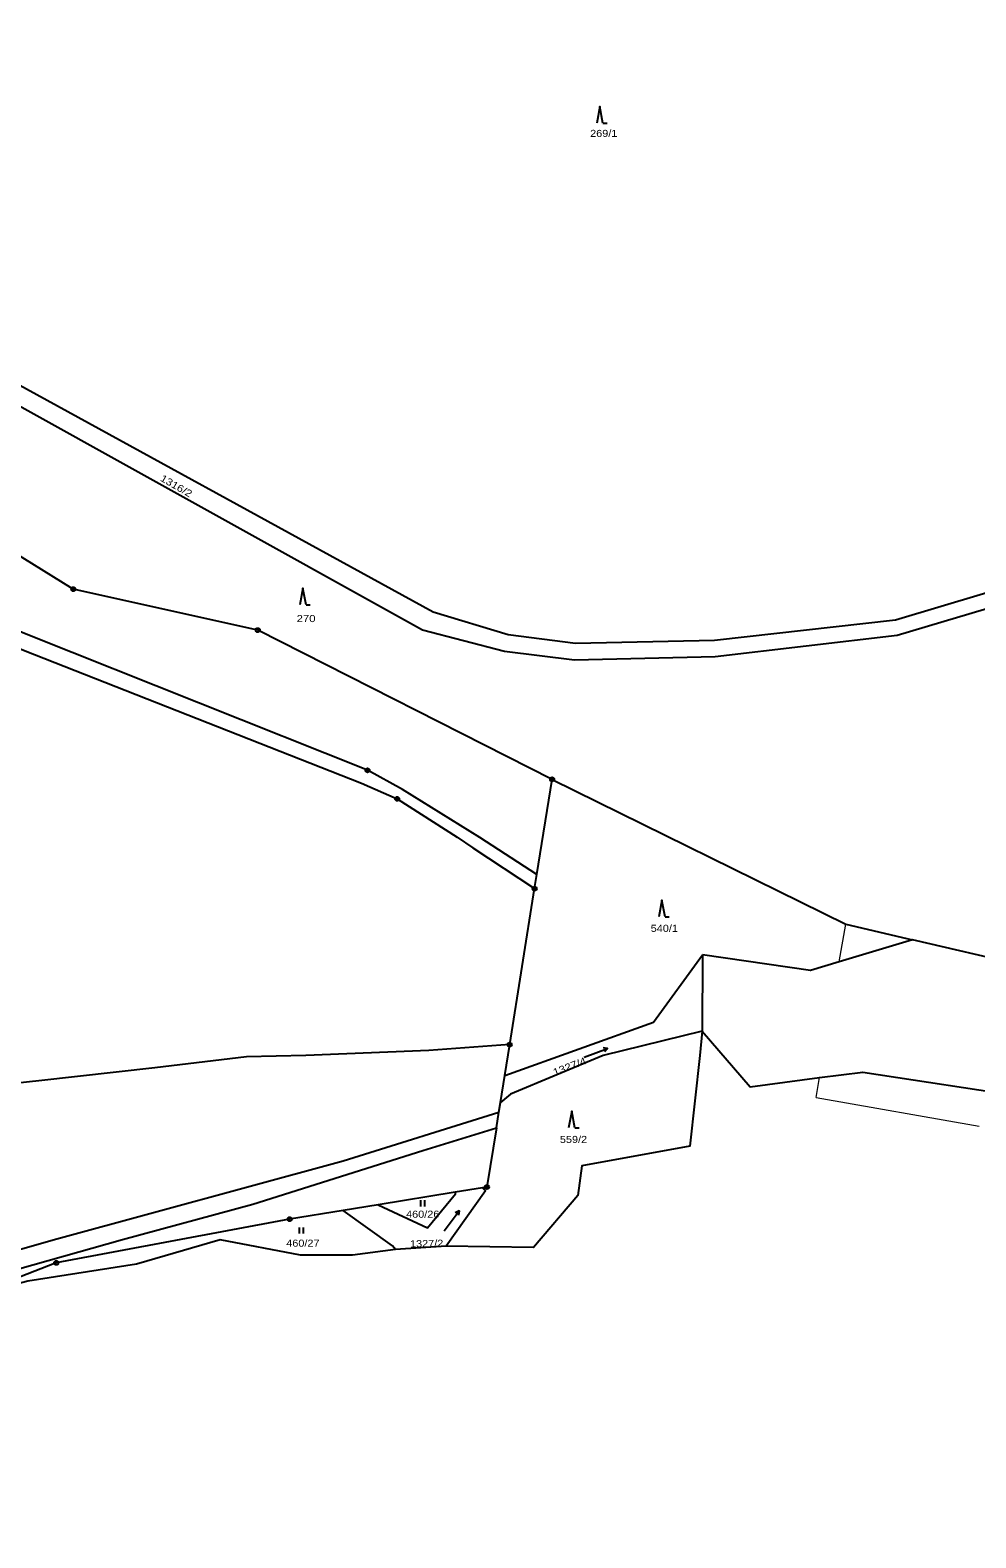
# Model space of a CAD drawing. Extents: x -872229 to -869198, y -1075981 to -1074329.
# Drawn here: x -869771.9 to -869544.7, y -1075316.1 to -1074953.6 of the extents above; entities that cross this region are included whole.
import ezdxf

# ---------------------------------------------------------------- set-up
doc = ezdxf.new("R2010")
doc.units = 0
doc.header["$LTSCALE"] = 0.68
for name, color, linetype, lineweight in [('1', 7, 'Continuous', 25), ('3', 7, 'Continuous', 25), ('4', 7, 'Continuous', 13), ('8', 7, 'Continuous', 25)]:
    doc.layers.add(name, color=color, linetype=linetype, lineweight=lineweight)
doc.layers.add('2', color=7, linetype='Continuous')

msp = doc.modelspace()

# ---------------------------------------------------------------- linework, layer by layer
at = {"layer": '1'}
for p, q in [((-869650.14, -1075156.59), (-869646.48, -1075133.71)), ((-869650.68, -1075159.97), (-869650.14, -1075156.59)), ((-869656.67, -1075197.48), (-869650.68, -1075159.97)), ((-869610.34, -1075175.92), (-869610.41, -1075194.26)), ((-869659.87, -1075217.53), (-869659.27, -1075213.75)), ((-869659.27, -1075213.75), (-869658.9, -1075211.43)), ((-869663.18, -1075231.88), (-869669.81, -1075232.97)), ((-869669.81, -1075232.97), (-869688.29, -1075235.98)), ((-869688.29, -1075235.98), (-869696.7, -1075237.35))]:
    msp.add_line(p, q, dxfattribs=at)
for points in [[(-869650.14, -1075156.59), (-869663.85, -1075147.72), (-869682.43, -1075136.12), (-869690.84, -1075131.53), (-869772.1, -1075099.13), (-869844.86, -1075069.32), (-869848.3, -1075067.94), (-869907.96, -1075043.15), (-869940.96, -1075028.98), (-869973.59, -1075015.13), (-869995.78, -1075005.14), (-870001.42, -1074998.91), (-870003.58, -1074990.56), (-870002.58, -1074982.27), (-870000.39, -1074972.48), (-869996.55, -1074953.58)], [(-869646.48, -1075133.71), (-869717.21, -1075097.82), (-869761.54, -1075087.98), (-869810.64, -1075057.49), (-869851.57, -1075052.75), (-869911.59, -1075031.3), (-869976.94, -1074996.08), (-869983.15, -1074985.9), (-869984.78, -1074967.82), (-869973.47, -1074958.19)], [(-869479.66, -1075070.06), (-869480.79, -1075070.33), (-869510.31, -1075083.29), (-869563.58, -1075099.14), (-869607.33, -1075104.27), (-869641.09, -1075105.05), (-869657.9, -1075102.95), (-869677.61, -1075097.87), (-869787.66, -1075036.73), (-869804.59, -1075028.78), (-869863.04, -1075007.07), (-869931.86, -1074972.77), (-869958.29, -1074958.82), (-869973.47, -1074958.19)], [(-869929.31, -1074968.38), (-869861.33, -1075003.43), (-869802.73, -1075024.51), (-869785.27, -1075033.02), (-869675.06, -1075093.42), (-869657.01, -1075098.88), (-869640.84, -1075100.95), (-869607.45, -1075100.23), (-869563.99, -1075095.38), (-869511.48, -1075079.68), (-869481.91, -1075066.7), (-869467.98, -1075063.1), (-869463.59, -1075063.5)], [(-870007.09, -1074982.34), (-870007.65, -1074991.46), (-870005.25, -1074999.97), (-870000.07, -1075005.82), (-869979.18, -1075015.56), (-869947.14, -1075029.34), (-869914.15, -1075043.78), (-869849.68, -1075071.21), (-869846.22, -1075072.58), (-869773.51, -1075102.64), (-869692.27, -1075134.64), (-869683.71, -1075138.39), (-869669.29, -1075147.62), (-869665.53, -1075150.2), (-869650.68, -1075159.97)], [(-869646.48, -1075133.71), (-869575.93, -1075168.51), (-869559.89, -1075172.26)], [(-869460.16, -1075167.77), (-869533.72, -1075178.38), (-869559.89, -1075172.26), (-869577.48, -1075177.56)], [(-869657.86, -1075204.9), (-869622.14, -1075192.1), (-869610.34, -1075175.92)], [(-869577.48, -1075177.56), (-869584.37, -1075179.64), (-869610.34, -1075175.92)], [(-869656.67, -1075197.48), (-869676.11, -1075198.92), (-869705.7, -1075200.11), (-869719.96, -1075200.44), (-869741.96, -1075203.08), (-869769.79, -1075206.17), (-869793.73, -1075208.74), (-869802.97, -1075209.8), (-869816.06, -1075208.55), (-869855.81, -1075204.07), (-869887.65, -1075202.22), (-869902.63, -1075201.56), (-869926.76, -1075200.04), (-869936.33, -1075199.65), (-869949.18, -1075200.24), (-869974.1, -1075201.42), (-869979.65, -1075201.82), (-869989.18, -1075200.96), (-870032.43, -1075196.35), (-870040.36, -1075195.42)], [(-869610.41, -1075194.26), (-869610.95, -1075200.13), (-869613.36, -1075221.91), (-869639.34, -1075226.59), (-869640.32, -1075233.75), (-869650.96, -1075246.23), (-869671.93, -1075245.96), (-869684.1, -1075246.72)], [(-869610.41, -1075194.26), (-869634.23, -1075200.13), (-869656.49, -1075209.41), (-869658.9, -1075211.43)], [(-869610.41, -1075194.26), (-869598.91, -1075207.6), (-869582.25, -1075205.43), (-869571.84, -1075204.08), (-869531.81, -1075210.17)], [(-869658.9, -1075211.43), (-869657.86, -1075204.9), (-869656.67, -1075197.48)], [(-870385.12, -1075316.07), (-870355.23, -1075301.89), (-870314.21, -1075282.93), (-870280.58, -1075266.36), (-870265.86, -1075261.9), (-870249.15, -1075258.69), (-870230, -1075254.57), (-870219.5, -1075254.87), (-870207.6, -1075253.65), (-870190, -1075251.81), (-870178.96, -1075255.5), (-870167.23, -1075255.17), (-870141.46, -1075254.46), (-870092.41, -1075254.3), (-870019.81, -1075254.06), (-869952.16, -1075254.08), (-869902.23, -1075254.21), (-869809.43, -1075253.56), (-869784.98, -1075249.67), (-869765.49, -1075244.15), (-869696.7, -1075225.43), (-869659.27, -1075213.75)], [(-870086.74, -1075257.68), (-870033.35, -1075257.7), (-869997.08, -1075257.38), (-869953.96, -1075258.61), (-869925.38, -1075258.43), (-869886.31, -1075258.63), (-869811.48, -1075257.76), (-869785.54, -1075254.45), (-869749.68, -1075244.36), (-869718.38, -1075235.81), (-869677.56, -1075222.96), (-869659.87, -1075217.53)], [(-869659.87, -1075217.53), (-869662.14, -1075231.71), (-869663.18, -1075231.88)], [(-869663.18, -1075231.88), (-869662.47, -1075232.67), (-869671.93, -1075245.96)], [(-869688.29, -1075235.98), (-869676.45, -1075241.57), (-869669.7, -1075233.33), (-869669.81, -1075232.97)], [(-869709.56, -1075239.45), (-869765.65, -1075249.96), (-869788.46, -1075258.83)], [(-869684.1, -1075246.72), (-869684.85, -1075245.87), (-869696.7, -1075237.35), (-869709.56, -1075239.45)], [(-869684.1, -1075246.72), (-869694.41, -1075248.14), (-869706.94, -1075248.13), (-869726.28, -1075244.45), (-869746.39, -1075250.29), (-869772.5, -1075254.32), (-869779.17, -1075256.14), (-869786.75, -1075258.83)]]:
    msp.add_lwpolyline(points, dxfattribs=at)
at = {"layer": '3'}
for p, q in [((-869634.27, -1074975.95), (-869633.274, -1074975.95)), ((-869705.61, -1075091.77), (-869704.614, -1075091.77)), ((-869619.35, -1075166.75), (-869618.354, -1075166.75)), ((-869633.152, -1075198.426), (-869633.899, -1075199.232)), ((-869641.01, -1075217.5), (-869640.014, -1075217.5)), ((-869678.051, -1075236.4), (-869678.051, -1075234.9)), ((-869677.05, -1075236.4), (-869677.05, -1075234.9)), ((-869668.807, -1075237.446), (-869668.995, -1075238.528)), ((-869707.201, -1075242.92), (-869707.201, -1075241.42)), ((-869706.2, -1075242.92), (-869706.2, -1075241.42))]:
    msp.add_line(p, q, dxfattribs=at)
for points in [[(-869634.27, -1074975.95), (-869635.02, -1074971.95), (-869635.77, -1074975.95)], [(-869705.61, -1075091.77), (-869706.36, -1075087.77), (-869707.11, -1075091.77)], [(-869619.35, -1075166.75), (-869620.1, -1075162.75), (-869620.85, -1075166.75)], [(-869638.79, -1075200.478), (-869633.152, -1075198.426), (-869634.242, -1075198.289)], [(-869641.01, -1075217.5), (-869641.76, -1075213.5), (-869642.51, -1075217.5)], [(-869672.418, -1075242.237), (-869668.807, -1075237.446), (-869669.796, -1075237.924)]]:
    msp.add_lwpolyline(points, dxfattribs=at)
at = {"layer": '4'}
for p, q in [((-869577.48, -1075177.56), (-869575.93, -1075168.51)), ((-869583.06, -1075210.18), (-869582.25, -1075205.43)), ((-869583.06, -1075210.18), (-869543.86, -1075217.07))]:
    msp.add_line(p, q, dxfattribs=at)
at = {"layer": '8'}
for centre, radius in [((-869761.54, -1075087.9799), 0.5), ((-869761.54, -1075087.9799), 0.0303), ((-869717.21, -1075097.8199), 0.5), ((-869717.21, -1075097.8199), 0.0303), ((-869690.84, -1075131.5299), 0.5), ((-869690.84, -1075131.5299), 0.0303), ((-869646.48, -1075133.7099), 0.5), ((-869646.48, -1075133.7099), 0.0303), ((-869683.71, -1075138.3899), 0.5), ((-869683.71, -1075138.3899), 0.0303), ((-869650.68, -1075159.9699), 0.5), ((-869650.68, -1075159.9699), 0.0303), ((-869656.67, -1075197.4799), 0.5), ((-869656.67, -1075197.4799), 0.0303), ((-869662.14, -1075231.7099), 0.5), ((-869662.14, -1075231.7099), 0.0303), ((-869709.56, -1075239.4499), 0.5), ((-869709.56, -1075239.4499), 0.0303), ((-869765.65, -1075249.9599), 0.5), ((-869765.65, -1075249.9599), 0.0303)]:
    msp.add_circle(centre, radius, dxfattribs=at)

# ---------------------------------------------------------------- texts
at = {"layer": '2'}
for s, width, p in [('269/1', 1.15, (-869637.34, -1074979.25)), ('270', 1.2, (-869707.88, -1075095.9)), ('540/1', 1.15, (-869622.79, -1075170.37)), ('559/2', 1.15, (-869644.61, -1075221.13)), ('460/26', 1.15, (-869681.57, -1075239.11)), ('460/27', 1.15, (-869710.37, -1075246.07))]:
    msp.add_text(s, height=1.7, dxfattribs=dict(at, width=width)).set_placement(p)
for s, rotation, width, p in [('1316/2', 330, 1.2, (-869740.825, -1075061.806)), ('1327/4', 21, 1.2, (-869645.895, -1075205.013)), ('1327/2', 1, 1.15, (-869680.605, -1075246.219))]:
    msp.add_text(s, height=1.7, rotation=rotation, dxfattribs=dict(at, width=width)).set_placement(p)

doc.saveas('drawing.dxf')
